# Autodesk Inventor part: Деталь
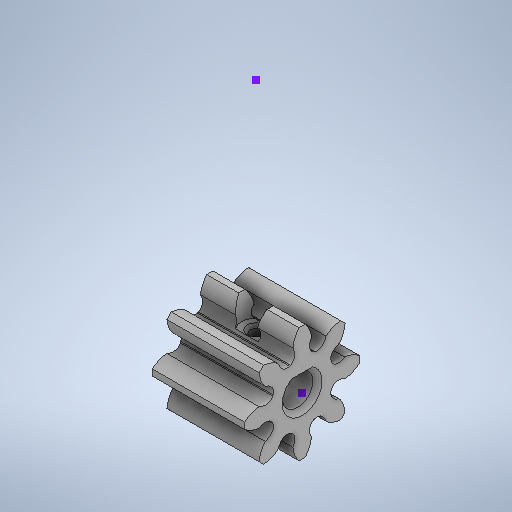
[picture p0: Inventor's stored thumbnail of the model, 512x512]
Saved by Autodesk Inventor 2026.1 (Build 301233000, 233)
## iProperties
Company: UNSPECIFIED
Created: 1900-01
Part Number: Деталь
Material: Типовые
Description: STEP AP203
Document SubType Name: Modeling
Designer: Yury Melnikov
Density: 1 g/cm^3
Appearance: По умолчанию
Sending System: C3D Toolkit
Preprocessor: C3D Converter
Title: Äåòàëü
Author: UNSPECIFIED
Revision Number: ANYUNSPECIFIED
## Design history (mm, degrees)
node "Исправленная геометрия1"
  sketch "3D эскиз1"
  node "3D эскиз2"
  node "3D эскиз3"
  node "3D эскиз4"
  sketch "3D эскиз5"
  node "3D эскиз6"
feature "БазТело1"
sketch "Эскиз1"
  geometry: L1 (-1.549, 2.15)-(1.549, 2.15); A1 r 2.65 centre (0, 0) between (-1.549, 2.15) and (1.549, 2.15); 1 further point
  constraints: 2 end point, 2 point on circle, 1 centre point, 1 coincident, 1 horizontal
  dimensions: "d0" = 5.3 diameter of A1; "d1" = 4.8 dimension on A1 L1
extrude "Выдавливание1" cut sketch "Эскиз1" distance "d2" = 20; taper "d3" = 0 deg
sketch "Эскиз2"
  geometry: L1 (-16, 8.992)-(0, 8.992) reference; C1 r 1 at (-8, 1.549); 2 further points
  constraints: 1 centre point, 1 horizontal alignment, 1 midpoint, 1 vertical alignment
  dimensions: "d4" = 2 diameter of C1
extrude "Выдавливание2" cut sketch "Эскиз2" distance "d5" = 20; taper "d6" = 0 deg
node "РабПлоскость1"
sketch "Эскиз3"
  geometry: C1 r 1 at (-8, 1.549) reference; C2 r 2.5 at (-8, 1.549); 5 further points
  constraints: 2 horizontal alignment, 2 vertical alignment, 1 centre point, 1 coincident
  dimensions: "d8" = 5 diameter of C2
extrude "Выдавливание3" cut sketch "Эскиз3" distance "d9" = 20; taper "d10" = 0 deg
chamfer "Фаска1" distance "d11" = 0.5; stored, may be unused: second distance "d12" = 2, angle "d13" = 45 deg
chamfer "Фаска2" distance "d14" = 0.8; stored, may be unused: second distance "d15" = 2, angle "d16" = 45 deg
node "Твердое тело1"
node "Спроецированная петля1"
other parameters: "d7" = -3.25
